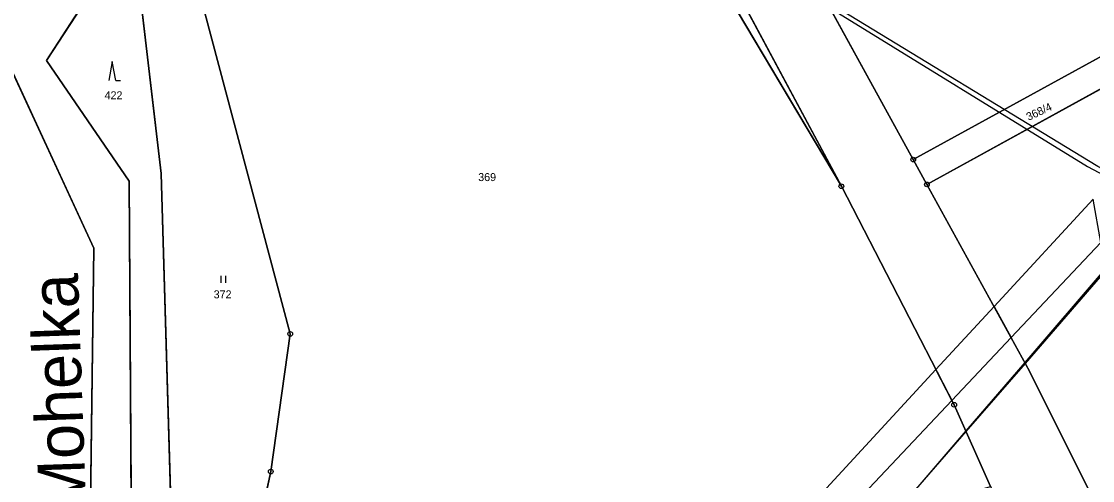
# Model space of a CAD drawing. Extents: x -689422 to -685210, y -987725 to -982160.
# Drawn here: x -686553.1 to -686325.7, y -986529.1 to -986431.6 of the extents above; entities that cross this region are included whole.
import ezdxf

# ---------------------------------------------------------------- set-up
doc = ezdxf.new("R2010")
doc.units = 0
for name, color, linetype in [('KN_Hranice_parcel', 7, 'Continuous'), ('KN_Parcelni cisla', 7, 'Continuous'), ('KN_Polygon parcely', 7, 'Continuous'), ('KN_Popisy_pomistni nazvy vodni toky', 7, 'Continuous'), ('KN_POZEMKY_LESNI POZEMEK', 7, 'Continuous'), ('KN_POZEMKY_ORNA PUDA', 7, 'Continuous'), ('KN_POZEMKY_OSTATNI PLOCHA', 7, 'Continuous'), ('KN_POZEMKY_TTP', 7, 'Continuous'), ('KN_POZEMKY_VODNI_PLOCHA', 7, 'Continuous'), ('KN_VYUZITI_07_vodni plocha_tok prirozeny', 7, 'Continuous'), ('KN_VYUZITI_16_ostatni plocha_silnice', 7, 'Continuous'), ('KN_Věcná břemena k části', 7, 'Continuous'), ('KN_Značky bodu BP', 7, 'Continuous'), ('KN_Značky kultur', 7, 'Continuous')]:
    doc.layers.add(name, color=color, linetype=linetype)

msp = doc.modelspace()

# ---------------------------------------------------------------- linework, layer by layer
at = {"layer": 'KN_Hranice_parcel'}
for p, q in [((-686379.02, -986466.59), (-686427.11, -986376.67)), ((-686379.02, -986466.59), (-686429.73, -986381.17)), ((-686363.74, -986460.93), (-686316.89, -986435.17)), ((-686360.85, -986466.19), (-686313.16, -986439.96)), ((-686360.85, -986466.19), (-686363.74, -986460.93))]:
    msp.add_line(p, q, dxfattribs=at)
for points in [[(-686363.74, -986460.93), (-686408.18, -986380.1), (-686426.63, -986346.03)], [(-686661.37, -986699.87), (-686649.57, -986677.34), (-686647.08, -986655.49), (-686618.08, -986627.04), (-686583.38, -986608.38), (-686575.7, -986594.43), (-686554.43, -986549.86), (-686538.67, -986550.05), (-686537.77, -986479.73), (-686558.79, -986434.27), (-686553.34, -986411.64)], [(-686529.76, -986542.24), (-686530.23, -986465.49), (-686547.77, -986439.87), (-686534.21, -986418.86)], [(-686524.3, -986419.33), (-686528.35, -986422.25), (-686523.48, -986463.86), (-686521.13, -986543.48), (-686517.08, -986543.59), (-686518.23, -986552.13)], [(-686514.16, -986429.75), (-686496.06, -986497.96), (-686500.18, -986527.22), (-686507.21, -986559.72)], [(-686281.05, -986622.22), (-686339.04, -986505.86), (-686360.85, -986466.19)], [(-686347.32, -986530.39), (-686355.06, -986513.03), (-686379.02, -986466.59)]]:
    msp.add_lwpolyline(points, dxfattribs=at)
at = {"layer": 'KN_Polygon parcely'}
for points in [[(-686679.56, -986210.72), (-686671.4, -986248.73), (-686644.68, -986241.46), (-686643.38, -986256.33), (-686632.23, -986279.81), (-686597.54, -986288.3), (-686596.93, -986298.95), (-686596.08, -986305.34), (-686570.29, -986348.74), (-686562.52, -986391.3), (-686560.8, -986399.5), (-686557.38, -986401.84), (-686553.34, -986411.64), (-686558.79, -986434.27), (-686537.77, -986479.73), (-686538.67, -986550.05)], [(-686529.76, -986542.24), (-686530.23, -986465.49), (-686547.77, -986439.87), (-686534.21, -986418.86), (-686537.43, -986399.99), (-686549.98, -986397.14), (-686553.27, -986362.5), (-686568.63, -986323.94), (-686584.5, -986302.4), (-686589.89, -986276.07), (-686619.99, -986268), (-686624.7, -986261.38), (-686636.01, -986217.82)], [(-686563.88, -986223.26), (-686544.95, -986241.07), (-686539.46, -986246.23), (-686522.08, -986260.86), (-686522.73, -986261.63), (-686512.36, -986270.37), (-686484.06, -986294.24), (-686474.22, -986304.87), (-686466.26, -986313.46), (-686461.64, -986320.02), (-686455.2, -986331.09), (-686444.9, -986347.8), (-686427.11, -986376.67), (-686379.02, -986466.59), (-686355.06, -986513.03), (-686347.32, -986530.39), (-686283.4, -986653.69)], [(-686281.05, -986622.22), (-686339.04, -986505.86), (-686360.85, -986466.19), (-686363.74, -986460.93), (-686408.18, -986380.1), (-686426.63, -986346.03), (-686439.22, -986324.23), (-686455.43, -986303.24), (-686459.36, -986298.16), (-686485.23, -986271.73), (-686500.94, -986258.37), (-686518.71, -986243.33), (-686534.93, -986229.71)]]:
    msp.add_lwpolyline(points, dxfattribs=at)
for points in [[(-686316.89, -986435.17), (-686338.86, -986407.01), (-686393.73, -986335.43), (-686426.63, -986346.03), (-686408.18, -986380.1), (-686363.74, -986460.93)], [(-686430.95, -986378.9), (-686429.73, -986381.17), (-686379.02, -986466.59), (-686427.11, -986376.67)], [(-686509.94, -986575.81), (-686511.01, -986578.37), (-686347.32, -986530.39), (-686355.06, -986513.03), (-686379.02, -986466.59), (-686429.73, -986381.17), (-686473.78, -986406.81), (-686500.62, -986419.59), (-686506.92, -986423.63), (-686514.16, -986429.75), (-686496.06, -986497.96), (-686500.18, -986527.22), (-686507.21, -986559.72)], [(-686649.57, -986677.34), (-686647.08, -986655.49), (-686618.08, -986627.04), (-686583.38, -986608.38), (-686575.7, -986594.43), (-686554.43, -986549.86), (-686538.67, -986550.05), (-686537.77, -986479.73), (-686558.79, -986434.27), (-686553.34, -986411.64), (-686638.13, -986432.16), (-686636.35, -986447.55), (-686632.91, -986464.58), (-686628.1, -986483.15), (-686642.45, -986479.17), (-686658.73, -986468.88), (-686659.13, -986474.94), (-686667.92, -986522.94), (-686676.51, -986555.42), (-686669.05, -986556.66), (-686698.87, -986657.84), (-686705.63, -986680.32), (-686661.37, -986699.87)], [(-686529.76, -986542.24), (-686518.23, -986552.13), (-686517.08, -986543.59), (-686521.13, -986543.48), (-686523.48, -986463.86), (-686528.35, -986422.25), (-686524.3, -986419.33), (-686524.34, -986415.16), (-686534.21, -986418.86), (-686547.77, -986439.87), (-686530.23, -986465.49)], [(-686528.35, -986422.25), (-686523.48, -986463.86), (-686521.13, -986543.48), (-686517.08, -986543.59), (-686518.23, -986552.13), (-686514.6, -986555.75), (-686509.24, -986560.47), (-686507.21, -986559.72), (-686500.18, -986527.22), (-686496.06, -986497.96), (-686514.16, -986429.75), (-686515.94, -986427.04), (-686524.3, -986419.33)], [(-686360.85, -986466.19), (-686313.16, -986439.96), (-686316.89, -986435.17), (-686363.74, -986460.93)], [(-686268.64, -986613.74), (-686263.17, -986592.87), (-686263.08, -986592.53), (-686245.48, -986525.43), (-686277.88, -986495.23), (-686293.56, -986465.08), (-686313.16, -986439.96), (-686360.85, -986466.19), (-686339.04, -986505.86), (-686281.05, -986622.22)]]:
    msp.add_lwpolyline(points, close=True, dxfattribs=at)
at = {"layer": 'KN_POZEMKY_LESNI POZEMEK'}
for p, q in [((-686547.77, -986439.87), (-686534.21, -986418.86)), ((-686528.35, -986422.25), (-686523.48, -986463.86)), ((-686530.23, -986465.49), (-686547.77, -986439.87)), ((-686523.48, -986463.86), (-686521.13, -986543.48)), ((-686529.76, -986542.24), (-686530.23, -986465.49))]:
    msp.add_line(p, q, dxfattribs=at)
at = {"layer": 'KN_POZEMKY_ORNA PUDA'}
for p, q in [((-686429.73, -986381.17), (-686379.02, -986466.59)), ((-686363.74, -986460.93), (-686408.18, -986380.1)), ((-686496.06, -986497.96), (-686514.16, -986429.75)), ((-686316.89, -986435.17), (-686363.74, -986460.93)), ((-686363.74, -986460.93), (-686316.89, -986435.17)), ((-686360.85, -986466.19), (-686313.16, -986439.96)), ((-686313.16, -986439.96), (-686360.85, -986466.19)), ((-686360.85, -986466.19), (-686363.74, -986460.93)), ((-686339.04, -986505.86), (-686360.85, -986466.19)), ((-686379.02, -986466.59), (-686355.06, -986513.03)), ((-686500.18, -986527.22), (-686496.06, -986497.96)), ((-686281.05, -986622.22), (-686339.04, -986505.86)), ((-686355.06, -986513.03), (-686347.32, -986530.39)), ((-686507.21, -986559.72), (-686500.18, -986527.22))]:
    msp.add_line(p, q, dxfattribs=at)
at = {"layer": 'KN_POZEMKY_OSTATNI PLOCHA'}
for p, q in [((-686379.02, -986466.59), (-686427.11, -986376.67)), ((-686408.18, -986380.1), (-686363.74, -986460.93)), ((-686363.74, -986460.93), (-686360.85, -986466.19)), ((-686360.85, -986466.19), (-686339.04, -986505.86)), ((-686355.06, -986513.03), (-686379.02, -986466.59)), ((-686339.04, -986505.86), (-686281.05, -986622.22)), ((-686347.32, -986530.39), (-686355.06, -986513.03))]:
    msp.add_line(p, q, dxfattribs=at)
at = {"layer": 'KN_POZEMKY_TTP'}
for p, q in [((-686427.11, -986376.67), (-686379.02, -986466.59)), ((-686379.02, -986466.59), (-686429.73, -986381.17)), ((-686523.48, -986463.86), (-686528.35, -986422.25)), ((-686514.16, -986429.75), (-686496.06, -986497.96)), ((-686558.79, -986434.27), (-686537.77, -986479.73)), ((-686521.13, -986543.48), (-686523.48, -986463.86)), ((-686537.77, -986479.73), (-686538.67, -986550.05)), ((-686496.06, -986497.96), (-686500.18, -986527.22)), ((-686500.18, -986527.22), (-686507.21, -986559.72))]:
    msp.add_line(p, q, dxfattribs=at)
at = {"layer": 'KN_POZEMKY_VODNI_PLOCHA'}
for p, q in [((-686534.21, -986418.86), (-686547.77, -986439.87)), ((-686537.77, -986479.73), (-686558.79, -986434.27)), ((-686547.77, -986439.87), (-686530.23, -986465.49)), ((-686530.23, -986465.49), (-686529.76, -986542.24)), ((-686538.67, -986550.05), (-686537.77, -986479.73))]:
    msp.add_line(p, q, dxfattribs=at)
at = {"layer": 'KN_VYUZITI_07_vodni plocha_tok prirozeny'}
for p, q in [((-686534.21, -986418.86), (-686547.77, -986439.87)), ((-686537.77, -986479.73), (-686558.79, -986434.27)), ((-686547.77, -986439.87), (-686530.23, -986465.49)), ((-686530.23, -986465.49), (-686529.76, -986542.24)), ((-686538.67, -986550.05), (-686537.77, -986479.73))]:
    msp.add_line(p, q, dxfattribs=at)
at = {"layer": 'KN_VYUZITI_16_ostatni plocha_silnice'}
for p, q in [((-686379.02, -986466.59), (-686427.11, -986376.67)), ((-686408.18, -986380.1), (-686363.74, -986460.93)), ((-686363.74, -986460.93), (-686360.85, -986466.19)), ((-686360.85, -986466.19), (-686339.04, -986505.86)), ((-686355.06, -986513.03), (-686379.02, -986466.59)), ((-686339.04, -986505.86), (-686281.05, -986622.22)), ((-686347.32, -986530.39), (-686355.06, -986513.03))]:
    msp.add_line(p, q, dxfattribs=at)
at = {"layer": 'KN_Věcná břemena k části'}
for points in [[(-686282.87, -986485.63), (-686283.47, -986484.47), (-686324.56, -986462.41), (-686382.23, -986427.29), (-686381.47, -986428.69), (-686326.76, -986462.4)], [(-686323.94, -986478.57), (-686325.55, -986469.33), (-686346.58, -986492.14), (-686342.95, -986498.75)], [(-686322.62, -986484.3), (-686322.97, -986484.11), (-686340.06, -986504.01), (-686339.93, -986504.24)], [(-686342.95, -986498.75), (-686346.58, -986492.14), (-686358.93, -986505.53), (-686355.54, -986512.11)], [(-686339.93, -986504.24), (-686340.06, -986504.01), (-686352.58, -986518.59), (-686352.52, -986518.73)], [(-686355.54, -986512.11), (-686358.93, -986505.53), (-686394.63, -986544.26), (-686382.46, -986540.69)], [(-686352.52, -986518.73), (-686352.58, -986518.59), (-686367.87, -986536.41)]]:
    msp.add_lwpolyline(points, close=True, dxfattribs=at)
at = {"layer": 'KN_Značky bodu BP'}
for centre, radius in [((-686363.74, -986460.93), 0.5), ((-686363.74, -986460.93), 0.0303), ((-686379.02, -986466.59), 0.5), ((-686360.85, -986466.19), 0.5), ((-686360.85, -986466.19), 0.0303), ((-686379.02, -986466.59), 0.0303), ((-686496.06, -986497.96), 0.5), ((-686496.06, -986497.96), 0.0303), ((-686355.06, -986513.03), 0.5), ((-686355.06, -986513.03), 0.0303), ((-686500.18, -986527.22), 0.5), ((-686500.18, -986527.22), 0.0303)]:
    msp.add_circle(centre, radius, dxfattribs=at)
at = {"layer": 'KN_Značky kultur'}
for p, q in [((-686533.84, -986440.11), (-686534.59, -986444.11)), ((-686533.09, -986444.11), (-686533.84, -986440.11)), ((-686533.09, -986444.11), (-686532.09, -986444.11)), ((-686510.69, -986487.1), (-686510.69, -986485.6)), ((-686509.69, -986487.1), (-686509.69, -986485.6))]:
    msp.add_line(p, q, dxfattribs=at)

# ---------------------------------------------------------------- texts
at = {"layer": 'KN_Parcelni cisla'}
for s, p in [('422', (-686535.47, -986448.11)), ('369', (-686456.13, -986465.49)), ('372', (-686512.31, -986490.41))]:
    msp.add_text(s, height=1.7, dxfattribs=at).set_placement(p)
msp.add_text('368/4', height=1.7, rotation=25, dxfattribs=at).set_placement((-686339.27, -986452.71))
at = {"layer": 'KN_Popisy_pomistni nazvy vodni toky'}
msp.add_text('Mohelka', height=10, rotation=92, dxfattribs=at).set_placement((-686539.38, -986535.52))

doc.saveas('drawing.dxf')
